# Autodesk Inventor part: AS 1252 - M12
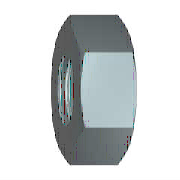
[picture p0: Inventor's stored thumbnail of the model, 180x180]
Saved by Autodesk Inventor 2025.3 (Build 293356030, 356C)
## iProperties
IsCustomPart: 0
Created: 2024-01
Part Number: AS 1252 - M12
Material: Acero, suave
Description: Pernos de acero Perno hex
Document SubType Name: Modeling
Standard: AS 1252
Designer: User
Standards Organization: AS
Language: es-ES
Size Designation: M12
Categories: <MemberInstance><Categories><Category DisplayName="Fijaciones" InternalName="e4da775c-781d-43d5-af7c-5136215cf5a6" Mnemonic="FSTN"><Category DisplayName="Tuerca
Density: 7.85 g/cm^3
Appearance: Semipulido
Author: User
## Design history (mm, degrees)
workaxis "Work Axis1"
workplane "Work Plane1"
sketch "Boceto1"
  geometry: L1 (-12.124, 0)-(-6.062, 10.5); L2 (-6.062, 10.5)-(6.062, 10.5); L3 (6.062, 10.5)-(12.124, 0); L4 (12.124, 0)-(6.062, -10.5); L5 (6.062, -10.5)-(-6.062, -10.5); L6 (-6.062, -10.5)-(-12.124, 0); 2 further points
  constraints: 12 end point, 1 coincident, 1 horizontal, 11 other
  dimensions: "d0" = 24.24871 distance of L3.end L1.start (= 1.1547 x SW)
extrude "Cuerpo" new body sketch "Boceto1" distance "d1" = 13.1 (= KOH); taper "d2" = 0 deg
revolve "Chaflán1" stored, may be unused: angle "d7" = 90 deg
sketch "Boceto3"
  geometry: A1 r 10.5 centre (0, 0) between (-5.25, -9.093) and (5.25, -9.093) reference; 1 further point
  constraints: 1 coincident
hole "Rosca" sketch "Boceto3" diameter "d25" = 10.106; stored, may be unused: countersink angle "d29" = 82 deg, drill point angle "d31" = 118 deg; dims "d26" = 6, "d27" = 4, "d28" = 2, "d30" = 8
body "Solid1"
chamfer "Chaflán2" distance "d8" = 0.94722 (= -0.5 x GD1 + 0.5 x NND); stored, may be unused: angle "d9" = 30 deg, second distance "d40" = 0.94722 (= -0.5 x GD1 + 0.5 x NND)
chamfer "Chaflán3" distance "d10" = 0.94722 (= -0.5 x GD1 + 0.5 x NND); stored, may be unused: angle "d11" = 30 deg, second distance "d41" = 0.94722 (= -0.5 x GD1 + 0.5 x NND)
sketch "Boceto2"
  geometry: L1 (0, 6.062)-(0, 12.124) reference; L2 (0, 12.124)-(13.1, 12.124) reference; L3 (13.1, 6.062)-(13.1, 12.124) reference; L4 (-2.62, 0)-(15.72, 0) reference; L5 (0.938, 12.124)-(0, 10.5); L6 (12.162, 12.124)-(13.1, 10.5)
  constraints: 4 end point, 4 point on line
  dimensions: "d3" = 30 deg angle of L1 L5 (= ANG1); "d4" = 30 deg angle of L3 L6 (= ANG2); "d5" = 21 diameter of L5.end L4 (= SW0); "d6" = 21 diameter of L6.end L4 (= SW01)
other parameters: "ANG1" = 30 deg [user parameter; used in 1 equation term], "ANG2" = 30 deg [user parameter; used in 1 equation term], "NND" = 12 [user parameter; used in 4 equation terms], "KOH" = 13.1 [user parameter; used in 1 equation term], "SW" = 21 [user parameter; used in 4 equation terms], "SW0" = 21 (= SW) [user parameter; used in 1 equation term], "SW01" = 21 (= SW) [user parameter; used in 1 equation term], "GD1" = 10.10557 (computed from THREADDIA, PTC, TOA) [user parameter; used in 4 equation terms], "d13" = 0, "d14" = 0, "d39" = 0, "d42" = 0, "GUL" = 0.94722 (= 0.541266 x PTC) [user parameter], "TPU" = 5.71429 (computed from PTC) [user parameter], "WFT" = 0.8 [user parameter], "THREADDIA" = 12 [user parameter; used in 1 equation term], "TOA" = 30 deg [user parameter; used in 1 equation term], "PTC" = 1.75 [user parameter; used in 4 equation terms], "E0" = 24.255 (= 1.155 x SW) [user parameter], "GAL" = 0.94722 (= 0.541266 x PTC) [user parameter]
